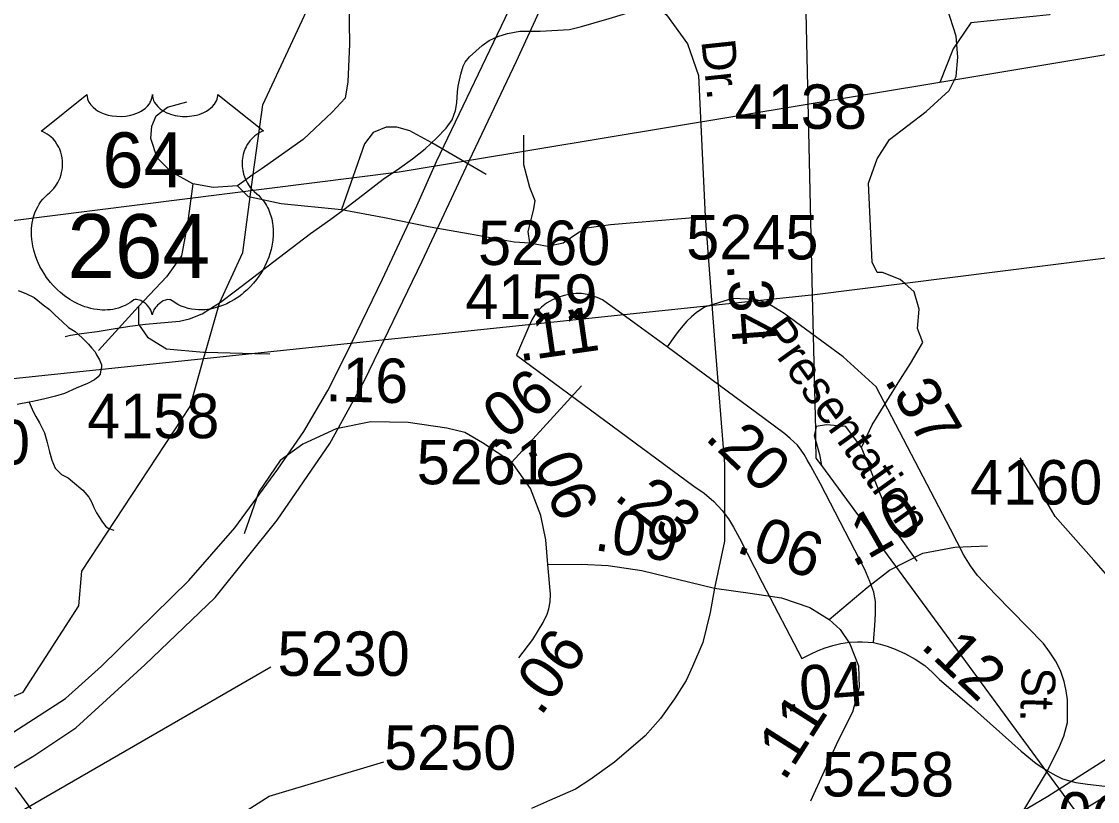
# Model space of a CAD drawing. Extents: x 2169602 to 2449496, y 721995 to 810662.
# Drawn here: x 2403022 to 2406048, y 800639 to 802833 of the extents above; entities that cross this region are included whole.
import ezdxf

# ---------------------------------------------------------------- set-up
doc = ezdxf.new("R2010")
doc.units = 0
doc.layers.add('Default', color=7, linetype='Continuous')

msp = doc.modelspace()

# ---------------------------------------------------------------- linework, layer by layer
at = {"layer": 'Default'}
for p, q in [((2405191.9, 804438.5), (2405245.3, 802063.2)), ((2406514.7, 802813), (2405604.6, 802661.9)), ((2403673.4, 802402.5), (2403629.2, 802370.9)), ((2403665, 802340), (2403673.4, 802402.5)), ((2405505.6, 802095.9), (2405245.3, 802063.2)), ((2405245.3, 802063.2), (2405254.3, 801683.9)), ((2403351, 802031), (2403237.8, 801907.9)), ((2403533.8, 801884.1), (2403539.1, 801902.8)), ((2403539.1, 801902.8), (2403677.6, 801899.2)), ((2403677.6, 801899.2), (2403720.3, 801898.1)), ((2405254.3, 801683.9), (2405254.9, 801655.7)), ((2405271.7, 801584), (2405489.9, 801286.9)), ((2405489.9, 801286.9), (2406019.8, 800565.3)), ((2403003.9, 800678.1), (2403553.4, 799929.9))]:
    msp.add_line(p, q, dxfattribs=at)
for points in [[(2400361.4, 799863.7), (2400990.3, 800043.5), (2401535.4, 800192.1), (2401961.6, 800311), (2402323.2, 800408.5), (2402465.8, 800457.7), (2402588.8, 800506.8), (2402756, 800585.5), (2402908.5, 800678.9), (2403056, 800767.4), (2403174.1, 800846), (2403368.5, 801023.3), (2403566.5, 801213), (2403740.2, 801430.3), (2403888.9, 801646), (2403986.1, 801823), (2404148, 802158.9), (2404272.5, 802423.1), (2404413.6, 802721.7), (2404509, 802930.5), (2404671, 803267.3), (2404731.9, 803402.6), (2404756.2, 803452.5)], [(2402635, 800622.9), (2402720.9, 800665.8), (2402892.7, 800766.8), (2403145.3, 800928.4), (2403246.3, 801019.3), (2403492, 801261.1), (2403621.9, 801409.1), (2403742.1, 801574), (2403815.4, 801679.6), (2403883.5, 801794.9), (2403937.1, 801902.9), (2404037.2, 802108.1), (2404133.5, 802315), (2404188.9, 802439.4), (2404403.6, 802887.8), (2404529.6, 803164.1), (2404635.6, 803381.7), (2404672, 803457.6)], [(2403377.2, 799750.9), (2404006.2, 799930.7), (2404551.3, 800079.3), (2404977.4, 800198.2), (2405339, 800295.7), (2405481.7, 800344.8), (2405604.6, 800394), (2405771.8, 800472.6), (2405924.3, 800566), (2406071.9, 800654.5), (2406189.9, 800733.2), (2406384.3, 800910.5), (2406582.3, 801100.2), (2406756.1, 801317.5), (2406904.8, 801533.2), (2407002, 801710.2), (2407163.8, 802046.1), (2407288.3, 802310.2), (2407429.5, 802608.9), (2407524.8, 802817.7), (2407686.9, 803154.5), (2407747.7, 803289.7), (2407772, 803339.7)], [(2406030.3, 803208.1), (2406016.3, 803112.9), (2405962.2, 802979.9), (2405912.9, 802851.8), (2405691.4, 802829.7), (2405642.2, 802755.8), (2405604.6, 802661.9)], [(2403673.4, 802402.5), (2403700, 802598.9), (2403855.8, 802933.6)], [(2404750.1, 802919.9), (2404835.9, 802851.8), (2404895, 802770.2), (2404925.3, 802681.2), (2404944.7, 802284.3), (2404971.4, 801925.1), (2404998.6, 801588), (2404998.6, 801371.2), (2404970.8, 801239.3)], [(2403942.5, 802890.4), (2403944.2, 802769.8), (2403939.3, 802663.9), (2403931.9, 802617.1), (2403895, 802577.7), (2403813.8, 802501.4), (2403698.1, 802420.1), (2403673.4, 802402.5)], [(2404562.7, 802810.8), (2404596.8, 802819), (2404632.4, 802829), (2404674.5, 802841.3), (2404714.3, 802853.6), (2404756.3, 802867.9), (2404788.1, 802878.1), (2404834, 802896.3), (2404858.2, 802905.6)], [(2405505.6, 802095.9), (2405492.5, 802107.4), (2405443.3, 802127.1), (2405428.5, 802127.1), (2405413.8, 802156.6), (2405403.9, 802378.3), (2405428.5, 802447.2), (2405463, 802501.4), (2405566.4, 802580.2), (2405630.4, 802639.3), (2405650.1, 802678.7), (2405655, 802732.9), (2405650.1, 802792), (2405625.4, 802870.8)], [(2403144, 801946.8), (2403159.8, 801950.8), (2403189.9, 801955.2), (2403234, 801961.5), (2403274, 801967.6), (2403326.1, 801976), (2403369.9, 801981.9), (2403466.1, 801990.5), (2403494, 801996.8), (2403529.5, 802010.9), (2403545.5, 802021.1), (2403581.6, 802043.2), (2403623.4, 802075.4), (2403762.8, 802182.1), (2403834.4, 802236.6), (2403892, 802277), (2403931.8, 802307), (2403989.4, 802351.5), (2404039.2, 802389.8), (2404085, 802420.2), (2404121.3, 802446.4), (2404156.5, 802474.7), (2404188.3, 802504.8), (2404216.4, 802532.9), (2404232.4, 802556.9), (2404242.2, 802583), (2404246.1, 802604.7), (2404247.8, 802634.9), (2404249.6, 802650.9), (2404257.4, 802684.9), (2404263.8, 802707.1), (2404269.5, 802718.8), (2404281.2, 802733.3), (2404317.1, 802765.2), (2404337, 802779.6), (2404361, 802791.4), (2404388.8, 802799.8), (2404422.9, 802806), (2404454.9, 802806), (2404480.7, 802806.1), (2404562.7, 802810.8)], [(2405604.6, 802661.9), (2404083.8, 802409.4), (2402489.8, 802208.8)], [(2403503.3, 802376.9), (2403442.1, 802410.3), (2403402.7, 802449.7), (2403385.5, 802503.8), (2403387.9, 802538.3), (2403400.3, 802567.9), (2403432.3, 802592.5), (2403486.4, 802607.3)], [(2408620.5, 802549), (2407099.7, 802296.5), (2405505.6, 802095.9)], [(2404328.2, 802402.9), (2404175.6, 802491.5), (2404114.1, 802526), (2404077.2, 802535.9), (2404047.6, 802535.9), (2404010.7, 802521.1), (2403986.1, 802489.1), (2403921.3, 802304.1)], [(2404451.3, 802210.8), (2404446.4, 802242.8), (2404461.2, 802301.9), (2404466.1, 802329), (2404451.3, 802365.9), (2404434.1, 802430), (2404434.1, 802513.7)], [(2403503.3, 802376.9), (2403488.9, 802265), (2403471.6, 802173.9), (2403429.8, 802114.8), (2403351, 802031)], [(2403629.2, 802370.9), (2403560.3, 802365.9), (2403503.3, 802376.9)], [(2403629.2, 802370.9), (2403658.7, 802341.3), (2403665, 802340)], [(2403539.1, 801902.8), (2403578, 802040.5), (2403643.8, 802183.5), (2403665, 802340)], [(2403665, 802340), (2403752.3, 802321.6), (2403921.3, 802304.1)], [(2403921.3, 802304.1), (2404042.7, 802282.2), (2404170.7, 802255.1), (2404283.9, 802235.4), (2404407, 802213.3), (2404451.3, 802210.8)], [(2404451.3, 802210.8), (2404500.5, 802200.9), (2404544.9, 802210.8), (2404589.2, 802240.3), (2404611.3, 802252.7), (2404677.8, 802262.5), (2404944.7, 802284.3)], [(2405384.2, 801634.6), (2405413.8, 801698.6), (2405487.6, 801816.8), (2405522.1, 801871), (2405556.5, 801930.1), (2405541.8, 801969.5), (2405546.7, 802023.6), (2405531.9, 802072.9), (2405505.6, 802095.9)], [(2382114, 799598.5), (2384855.4, 799926.8), (2405243.4, 802064.2)], [(2403011.8, 802076.2), (2403033.4, 802068.1), (2403057.4, 802056.4), (2403082.2, 802036.4), (2403100.2, 802022.7), (2403115.8, 802006.6), (2403136.3, 801988.9), (2403153.9, 801972.8), (2403172.4, 801961.1), (2403192.3, 801943.1), (2403210.3, 801925.4), (2403218.3, 801915.2), (2403228.8, 801903.5), (2403232.9, 801895.2), (2403240.7, 801881.4), (2403246.4, 801867.6), (2403246.8, 801861.5), (2403245, 801853.6), (2403242.9, 801841.3), (2403237, 801833.3), (2403226.7, 801825.5), (2403207.3, 801815.1), (2403175.1, 801801.3), (2403142.9, 801786.7), (2403117.4, 801778.8), (2403083.4, 801770.6), (2403053.5, 801764.5), (2403043.2, 801762.4)], [(2404837.4, 801917.6), (2404744.4, 801985.7), (2404689.7, 802025.7), (2404669.4, 802040), (2404655.7, 802049.9), (2404640.9, 802056.6), (2404627.4, 802061.1), (2404612.2, 802065.6), (2404596.9, 802067.8), (2404580.7, 802067.8), (2404565.9, 802066.5), (2404547.9, 802062.4), (2404530.4, 802057.1), (2404514.7, 802049.9), (2404498.4, 802040.9), (2404483.7, 802029.7), (2404472.9, 802018.4), (2404465.4, 802008.1), (2404456.7, 801993.8), (2404448.2, 801975.6), (2404413.4, 801894.4)], [(2403351, 802031), (2403351, 801981.8), (2403375.6, 801944.8), (2403429.8, 801912.8), (2403533.2, 801903), (2403539.1, 801902.8)], [(2405907.4, 800725.1), (2405941.2, 800793.7), (2405952.9, 800822.3), (2405963.4, 800860.9), (2405963.9, 800897.3), (2405963.9, 800924.9), (2405959.9, 800950.6), (2405953.9, 800976.2), (2405944.2, 801007.8), (2405929.4, 801034.4), (2405912.7, 801060), (2405895.7, 801083.1), (2405760.7, 801220.8), (2405710.4, 801275.1), (2405690.7, 801301.7), (2405671.9, 801332.3), (2405652.2, 801370.8), (2405634.4, 801405.3), (2405425.4, 801805.9), (2405332.2, 801889.8), (2405166.4, 802011.9), (2405117.4, 802041.3), (2405085.4, 802050.9), (2405021.4, 802053.6), (2404942.4, 802029.6), (2404918.9, 802013.4), (2404905.7, 802002.1), (2404892.9, 801989.9), (2404881.2, 801976.6), (2404868.7, 801961.5), (2404858.4, 801946.6), (2404837.4, 801917.6)], [(2405417.7, 801085.9), (2405421.9, 801134.3), (2405423.2, 801166.9), (2405423.9, 801201.2), (2405418.7, 801227.9), (2405407.9, 801258.2), (2405393.7, 801291.2), (2405268.9, 801532.2), (2405241.4, 801582.5), (2405231.4, 801600.3), (2405222.7, 801615.5), (2405214.7, 801627.1), (2405203.9, 801641.3), (2405183.9, 801660.1), (2405168.7, 801672.9), (2405110.7, 801716.8), (2404837.4, 801917.6)], [(2401167.1, 799779.9), (2401191, 799812.7), (2401355.8, 800147.2), (2401479.9, 800272.6), (2402004, 800373.4), (2402435.8, 800692.6), (2402776.9, 800803.7), (2402850.9, 800871.1), (2403026, 800946.3), (2403182.9, 801189.1), (2403190.8, 801287.3), (2403496, 801750.2), (2403533.8, 801884.1)], [(2404413.4, 801894.4), (2404912.7, 801526.4), (2404941.4, 801506), (2404968.4, 801482.6), (2404991.9, 801457.8), (2405009.9, 801434.4), (2405024.4, 801410.3), (2405040.9, 801380.1), (2405104.9, 801254.9), (2405216.7, 801041.5)], [(2404400.2, 801593.5), (2404596.2, 801807.9)], [(2403043.2, 801762.4), (2403009.6, 801756.2)], [(2403043.2, 801762.4), (2403053.9, 801736.5), (2403061.7, 801722.3), (2403071.9, 801704.5), (2403085.9, 801676.4), (2403094.1, 801648.5), (2403100.4, 801622.8), (2403106.6, 801598.7), (2403116.4, 801576.9), (2403134.3, 801558.8), (2403152.7, 801549.1), (2403164.6, 801539.2), (2403194.5, 801515.2), (2403210.9, 801495.3), (2403218.7, 801481.5), (2403225.1, 801465.6), (2403232.9, 801451.4), (2403241.3, 801437.6), (2403247.2, 801427.8), (2403257.7, 801413.6), (2403265.5, 801407.5), (2403281.5, 801401.9)], [(2404400.2, 801593.5), (2404318.2, 801647.5), (2404268.7, 801676.9), (2404217.9, 801689.6), (2404109.1, 801705.2), (2404004.5, 801707.3), (2403906.1, 801687.4), (2403813, 801644.5), (2403748.7, 801598.4), (2403689, 801510.5), (2403648.2, 801392.1)], [(2405384.2, 801634.6), (2405339.9, 801693.7), (2405285.8, 801698.6), (2405256.2, 801693.7), (2405254.3, 801683.9)], [(2405254.3, 801683.9), (2405251.3, 801669), (2405254.9, 801655.7)], [(2405254.9, 801655.7), (2405266.1, 801614.9), (2405271.7, 801584)], [(2405254.9, 801655.7), (2405256.1, 801605.2), (2405271.7, 801584)], [(2405540.5, 801315.1), (2405477.8, 801403.1), (2405384.2, 801634.6)], [(2406244.7, 800673.4), (2406242.4, 800966.9), (2406240.7, 801018.9), (2406229.7, 801064.6), (2406215.7, 801102.4), (2406190.4, 801143.3), (2406149.4, 801190.5), (2406037.7, 801318), (2405929.2, 801440.8), (2405881.9, 801521.1), (2405829.9, 801606.1)], [(2404502.1, 801305.2), (2404496, 801374.7), (2404482.2, 801443.7), (2404452.9, 801519.4), (2404400.2, 801593.5)], [(2405293.1, 801151.3), (2405399.9, 801241.4), (2405462.6, 801289.5), (2405556.8, 801337.7), (2405646.8, 801354.4), (2405738.9, 801358.6)], [(2404420.2, 801042.9), (2404459.8, 801094.5), (2404489.1, 801142.6), (2404499.7, 801165.9), (2404504.3, 801181.3), (2404508.2, 801200.6), (2404509.7, 801221.8), (2404502.1, 801305.2)], [(2404502.1, 801305.2), (2404595.7, 801306.3), (2404671.5, 801302.5), (2404766.2, 801288.7), (2404970.8, 801239.3)], [(2404970.8, 801239.3), (2404958.4, 801170.4), (2404937.9, 801086.2), (2404909.1, 801018.5), (2404890.6, 800979.5), (2404857.8, 800928.2), (2404818.8, 800872.8), (2404775.7, 800823.5), (2404689, 800749.8), (2404619.7, 800699.6), (2404579.4, 800673.8), (2404506.6, 800641.4), (2404456.2, 800619)], [(2404970.8, 801239.3), (2405071.3, 801224.6), (2405159.2, 801212), (2405238.7, 801184.8), (2405293.1, 801151.3)], [(2405293.1, 801151.3), (2405324.4, 801122.7), (2405351.2, 801082.2), (2405375.4, 801020.7), (2405377.5, 800960.8), (2405358.5, 800890.6), (2405317.7, 800808.9), (2405240.3, 800640.3)], [(2405216.7, 801041.5), (2405240.2, 801053.4), (2405261.9, 801063.8), (2405282.2, 801071.4), (2405303.4, 801078.1), (2405325.7, 801083.3), (2405350.7, 801087), (2405372.4, 801088.1), (2405386.4, 801088.4), (2405402.7, 801087.6), (2405417.7, 801085.9)], [(2405417.7, 801085.9), (2405436.9, 801081.6), (2405455.9, 801075.8), (2405479.2, 801067.8), (2405508.2, 801054.4), (2405535.4, 801039.8), (2405562.2, 801021.1), (2405583.4, 801001.4), (2405603.7, 800982.1), (2405693.2, 800905), (2405832.7, 800780.2), (2405874.9, 800745.8), (2405907.4, 800725.1)], [(2402493.1, 800188.8), (2402948.9, 800571), (2403722.5, 801017.6)], [(2403279.8, 799814.7), (2404050, 800023.8), (2404681.3, 800197.8), (2405036.8, 800292.1), (2405279.5, 800363.6), (2405393.2, 800401.5), (2405466.5, 800426.7), (2405532.1, 800454.5), (2405650.9, 800510.1), (2405736.7, 800553), (2405908.5, 800654), (2406161.1, 800815.5)], [(2402935.1, 800156.5), (2403717.9, 800653.8), (2404040.2, 800750.5)], [(2405126.7, 799462.4), (2405133.4, 799571.4), (2405135.7, 799638.5), (2405140.6, 799674.1), (2405158.4, 799711.7), (2405194, 799761.2), (2405320.5, 799927.3), (2405514.5, 800186.6), (2405707.9, 800428.3), (2405815.9, 800573.8), (2405907.4, 800725.1)], [(2405907.4, 800725.1), (2405930.7, 800711.8), (2405949.4, 800702.8), (2405965.9, 800697.6), (2405987.2, 800692.5), (2406019.9, 800687.8), (2406068.9, 800681.9), (2406138.4, 800676.6), (2406191.4, 800674.1), (2406244.7, 800673.4)]]:
    msp.add_lwpolyline(points, dxfattribs=at)
msp.add_lwpolyline([(2403205.6, 802627.5), (2403206, 802622.2), (2403207.2, 802615.9), (2403208.2, 802612.6), (2403211.2, 802606.4), (2403216.1, 802599), (2403222.9, 802591.8), (2403230.5, 802585.5), (2403235.7, 802582.1), (2403244.5, 802577.4), (2403254.4, 802573.2), (2403265.5, 802570), (2403276.8, 802567.8), (2403289.2, 802566.4), (2403301.4, 802566.2), (2403314.6, 802567.2), (2403329.2, 802570), (2403336, 802571.7), (2403343.5, 802574.3), (2403350.5, 802577.2), (2403358.2, 802581.3), (2403364.3, 802585.2), (2403369.1, 802588.7), (2403376, 802595.3), (2403381.4, 802602), (2403383.7, 802605.8), (2403385.6, 802609.5), (2403388.3, 802617.2), (2403389.1, 802620.7), (2403389.6, 802627.8), (2403390.1, 802621.8), (2403390.7, 802618.1), (2403391.7, 802614.4), (2403393.2, 802610.5), (2403395.9, 802605.1), (2403399, 802600.5), (2403404.7, 802593.8), (2403408.3, 802590.4), (2403411.5, 802587.8), (2403420.3, 802581.7), (2403430.5, 802576.6), (2403435.5, 802574.4), (2403440.7, 802572.6), (2403447.2, 802570.6), (2403454, 802569), (2403460.6, 802567.8), (2403467.5, 802566.9), (2403474.5, 802566.3), (2403480.2, 802566.2), (2403487.2, 802566.2), (2403493.6, 802566.6), (2403500.2, 802567.4), (2403507.5, 802568.6), (2403513.4, 802569.9), (2403521.1, 802571.9), (2403528.1, 802574.5), (2403534.2, 802577.1), (2403542.2, 802581.3), (2403548.7, 802585.3), (2403553.4, 802589.1), (2403559, 802594.3), (2403564.3, 802600.4), (2403567.4, 802604.9), (2403569.6, 802609.6), (2403571.7, 802614.4), (2403572.9, 802619.6), (2403573.5, 802624.1), (2403573.7, 802627.9), (2403702.3, 802525.5), (2403699.2, 802524.3), (2403692.2, 802520.9), (2403686.7, 802517.6), (2403677.9, 802511.4), (2403674.1, 802508), (2403670.3, 802504.4), (2403666.8, 802500.6), (2403663.7, 802497), (2403660, 802491.9), (2403656.6, 802486.7), (2403653.4, 802481), (2403651, 802476), (2403647, 802465.7), (2403645.1, 802459.2), (2403643.9, 802453.6), (2403642.4, 802442.2), (2403642, 802436.7), (2403642, 802431.3), (2403642.3, 802425.6), (2403642.8, 802420.1), (2403643.8, 802414.4), (2403644.7, 802409.4), (2403646.3, 802403.3), (2403648.6, 802396.1), (2403651.4, 802389.2), (2403657.3, 802378), (2403664.9, 802366.6), (2403670.3, 802360.2), (2403675.6, 802354.8), (2403683.5, 802348.1), (2403687.8, 802344.3), (2403692.7, 802339.3), (2403700.8, 802330), (2403704.1, 802325.6), (2403707.4, 802320.7), (2403710.4, 802315.6), (2403713.4, 802310.1), (2403715.9, 802305.3), (2403720.4, 802294.3), (2403723.7, 802283.6), (2403725.2, 802278), (2403727.6, 802265.3), (2403728.5, 802259.1), (2403729.5, 802246.8), (2403729.5, 802231.9), (2403728.4, 802217.8), (2403725.7, 802201.3), (2403723.5, 802191.4), (2403720.2, 802179.9), (2403716.9, 802170), (2403711, 802155.3), (2403705.8, 802144.7), (2403699, 802132.2), (2403694.4, 802124.7), (2403689, 802116.6), (2403682.3, 802107.4), (2403674.4, 802097.5), (2403664.9, 802087.1), (2403657.2, 802079.4), (2403647.2, 802070.4), (2403641.1, 802065.4), (2403632.4, 802058.9), (2403620.6, 802051), (2403608.9, 802044.2), (2403598.9, 802039.1), (2403590.1, 802035.3), (2403578.7, 802031), (2403559.8, 802025.8), (2403552.8, 802024.3), (2403544.6, 802023.1), (2403537, 802022.3), (2403529.5, 802021.9), (2403519.5, 802021.9), (2403509.6, 802022.6), (2403500.1, 802024), (2403490.3, 802026.1), (2403480.1, 802029.1), (2403470.8, 802032.7), (2403461.4, 802037.4), (2403445.5, 802047.4), (2403440.9, 802049.8), (2403438.3, 802050.5), (2403432.1, 802050.8), (2403426.4, 802049.6), (2403420.4, 802047.3), (2403416.9, 802045.4), (2403412.1, 802042.2), (2403408.5, 802039.4), (2403404.1, 802035.2), (2403401, 802031.7), (2403398.7, 802028.9), (2403394.2, 802021.9), (2403392.6, 802018.5), (2403391, 802014.2), (2403389.5, 802007.8), (2403387.5, 802015.9), (2403385.1, 802021.2), (2403382.4, 802025.8), (2403379.5, 802029.8), (2403375.1, 802034.9), (2403371, 802038.8), (2403366.2, 802042.8), (2403361, 802045.9), (2403356.9, 802048), (2403353.1, 802049.5), (2403348.4, 802050.6), (2403344.6, 802050.9), (2403341.5, 802050.8), (2403337.2, 802049.9), (2403331.4, 802045.7), (2403325.9, 802041.9), (2403319.9, 802038.1), (2403312.8, 802034.3), (2403307.5, 802031.9), (2403301.3, 802029.5), (2403294, 802027), (2403286.1, 802025), (2403278, 802023.4), (2403270.9, 802022.3), (2403263.2, 802021.6), (2403256.3, 802021.3), (2403249.1, 802021.4), (2403242.3, 802021.9), (2403234.5, 802022.6), (2403224.8, 802024.1), (2403216.7, 802025.9), (2403208.2, 802028.2), (2403199.5, 802030.9), (2403190.1, 802034.5), (2403178.4, 802039.6), (2403170.3, 802043.8), (2403157.5, 802051.1), (2403142.4, 802061.5), (2403131.1, 802070.7), (2403122.8, 802078.3), (2403110.5, 802090.7), (2403103.4, 802098.8), (2403092.1, 802113.4), (2403084.9, 802124), (2403080.2, 802131.7), (2403073.4, 802144.2), (2403069.6, 802152), (2403064.7, 802163.4), (2403060.9, 802173.8), (2403057.7, 802183.7), (2403056, 802190), (2403053.6, 802201), (2403052.1, 802208.9), (2403050.6, 802219.6), (2403049.8, 802230.9), (2403049.7, 802241.3), (2403050, 802250), (2403051, 802260.1), (2403052.7, 802270.8), (2403054.7, 802280), (2403056.6, 802286.6), (2403059.3, 802294.7), (2403062.9, 802303.6), (2403067.2, 802312.1), (2403071.2, 802319.1), (2403076.3, 802326.7), (2403081.3, 802333.2), (2403087.9, 802340.3), (2403094.7, 802346.9), (2403101, 802352), (2403108.4, 802359.3), (2403112.3, 802363.7), (2403117, 802369.8), (2403120.7, 802375.5), (2403123.7, 802380.6), (2403127.6, 802388.1), (2403129.9, 802393.8), (2403132.9, 802402.4), (2403134.4, 802408.5), (2403135.9, 802416.3), (2403136.9, 802423.7), (2403137.3, 802432.9), (2403137, 802440.5), (2403136.1, 802449.4), (2403134.4, 802457.9), (2403132.4, 802465.3), (2403129.2, 802473.8), (2403126.3, 802480.1), (2403121.3, 802488.5), (2403115.9, 802496.3), (2403110.2, 802502.7), (2403104.5, 802508.4), (2403099, 802512.7), (2403093.8, 802516.4), (2403087.3, 802520.3), (2403081, 802523.5), (2403077, 802525.1)], close=True, dxfattribs=at)

# ---------------------------------------------------------------- texts
for s, height, rotation, p in [('Dr.', 95, 276.1142, (2404933.3, 802778.4)), ('.34', 125, 274.2883, (2405005.1, 802150.5)), ('.11', 125, 8.1681, (2404421.5, 801876.7)), ('Presentation', 95, 305.6446, (2405093.9, 801958.7)), ('.16', 125, 358.4802, (2403875.4, 801765.1)), ('.06', 125, 37.363, (2404344.4, 801625.8)), ('.37', 125, 300.326, (2405446.6, 801824.5)), ('.20', 125, 316.5862, (2404940.5, 801659.7)), ('.06', 125, 293.2825, (2404442.1, 801633.3)), ('.23', 125, 322.5952, (2404684.4, 801491.5)), ('.10', 125, 29.6104, (2405361.3, 801296)), ('.09', 125, 351.2523, (2404629.6, 801346.8)), ('.06', 125, 340.3309, (2405027.4, 801341.9)), ('.06', 125, 54.2993, (2404481.8, 800876)), ('.12', 125, 316.5862, (2405546.9, 801074.2)), ('.04', 125, 4.4486, (2405167.7, 800891.2)), ('St.', 95, 267.9027, (2405835.7, 801018.9)), ('.11', 125, 57.4809, (2405167, 800692.8)), ('.06', 125, 354.9536, (2405885, 800548.7))]:
    msp.add_text(s, height=height, rotation=rotation, dxfattribs=at).set_placement(p)
for s, height, p in [('4138', 125, (2405027.5, 802531.2)), ('64', 155, (2403249.4, 802366.2)), ('264', 180, (2403150.4, 802111.3)), ('5260', 125, (2404305.6, 802148.1)), ('5245', 125, (2404891.1, 802163.8)), ('4159', 125, (2404269.5, 801996.6)), ('4158', 125, (2403206.3, 801660.9)), ('4160', 125, (2402673.6, 801587.3)), ('5261', 125, (2404133.1, 801531.3)), ('4160', 125, (2405689.4, 801474.4)), ('5230', 125, (2403741.6, 800992.4)), ('5250', 125, (2404041.3, 800728)), ('5258', 125, (2405272.7, 800653.1))]:
    msp.add_text(s, height=height, dxfattribs=at).set_placement(p)

doc.saveas('drawing.dxf')
